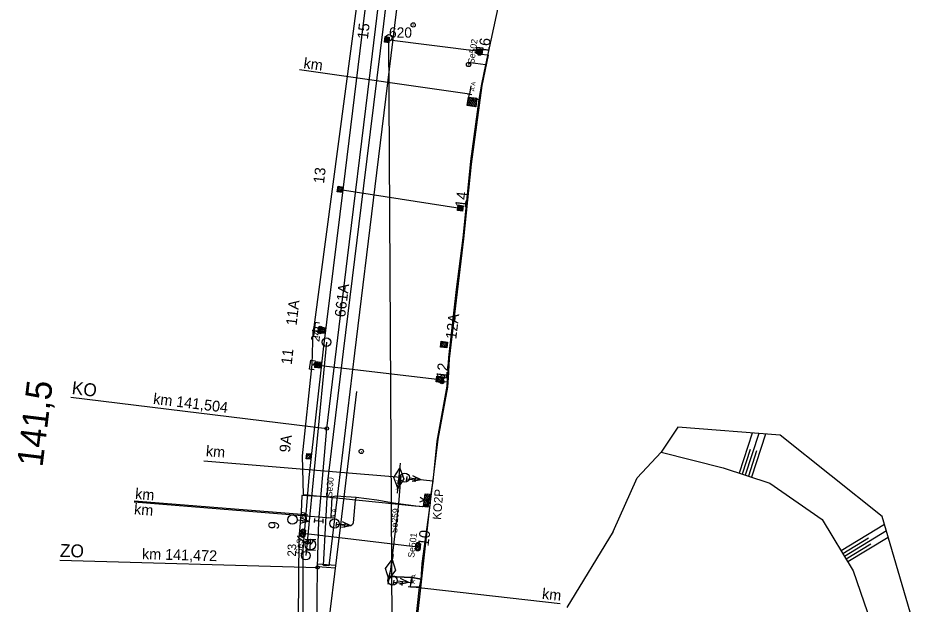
# Model space of a CAD drawing. Extents: x -598638 to -597933, y -1164002 to -1161904.
# Drawn here: x -598562.8 to -598354.3, y -1163078.8 to -1162942.3 of the extents above; entities that cross this region are included whole.
import ezdxf

# ---------------------------------------------------------------- set-up
doc = ezdxf.new("R2010")
doc.units = 0
for name, color, linetype in [('Vrstva 1', 7, 'Continuous'), ('Vrstva 11', 7, 'Continuous'), ('Vrstva 12', 7, 'Continuous'), ('Vrstva 17', 7, 'Continuous'), ('Vrstva 25', 7, 'Continuous'), ('Vrstva 26', 7, 'Continuous'), ('Vrstva 28', 7, 'Continuous'), ('Vrstva 3', 7, 'Continuous'), ('Vrstva 31', 7, 'Continuous'), ('Vrstva 35', 7, 'Continuous'), ('Vrstva 4', 7, 'Continuous'), ('Vrstva 43', 7, 'Continuous'), ('Vrstva 44', 7, 'Continuous'), ('Vrstva 48', 7, 'Continuous'), ('Vrstva 49', 7, 'Continuous'), ('Vrstva 51', 7, 'Continuous'), ('Vrstva 6', 7, 'Continuous'), ('Vrstva 63', 7, 'Continuous'), ('Vrstva 7', 7, 'Continuous')]:
    doc.layers.add(name, color=color, linetype=linetype)

msp = doc.modelspace()

# ---------------------------------------------------------------- linework, layer by layer
at = {"layer": 'Vrstva 1'}
for p, q in [((-598550.48, -1163030.61), (-598490.92, -1163037.88)), ((-598553.06, -1163068.55), (-598493.08, -1163070.23))]:
    msp.add_line(p, q, dxfattribs=at)
for points in [[(-598490.92, -1163037.88), (-598486.08, -1162998.23), (-598481.36, -1162959.57), (-598476.09, -1162916.14)], [(-598491.49, -1163091.37), (-598487.69, -1163060.3), (-598483.91, -1163029.31)], [(-598493.08, -1163070.23), (-598492.78, -1163059.37), (-598490.92, -1163037.88)], [(-598493.3, -1163091.17), (-598493.08, -1163070.23)]]:
    msp.add_lwpolyline(points, dxfattribs=at)
for centre in [(-598490.92, -1163037.88), (-598493.08, -1163070.23)]:
    msp.add_circle(centre, 0.4, dxfattribs=at)
at = {"layer": 'Vrstva 11'}
for p, q in [((-598476.84, -1162947.85), (-598477.38, -1162947.12)), ((-598476.53, -1162947.64), (-598477.08, -1162946.89)), ((-598476.95, -1162947.37), (-598455.4, -1162950.04)), ((-598455.51, -1162950.53), (-598455.9, -1162950)), ((-598454.98, -1162950.61), (-598455.82, -1162949.48)), ((-598454.9, -1162950.09), (-598455.3, -1162949.55)), ((-598487.95, -1162982.73), (-598488.34, -1162982.2)), ((-598487.42, -1162982.81), (-598488.26, -1162981.68)), ((-598487.84, -1162982.24), (-598459.89, -1162986.59)), ((-598487.34, -1162982.29), (-598487.74, -1162981.75)), ((-598460, -1162987.08), (-598460.39, -1162986.55)), ((-598459.47, -1162987.16), (-598460.31, -1162986.03)), ((-598459.39, -1162986.64), (-598459.79, -1162986.1)), ((-598492.14, -1163015.48), (-598492.55, -1163014.97)), ((-598491.61, -1163015.54), (-598492.49, -1163014.44)), ((-598491.55, -1163015.02), (-598491.96, -1163014.5)), ((-598463.22, -1163018.89), (-598464.1, -1163017.79)), ((-598463.16, -1163018.37), (-598463.58, -1163017.85)), ((-598463.75, -1163018.83), (-598464.16, -1163018.31)), ((-598493.03, -1163023.61), (-598493.44, -1163023.09)), ((-598492.5, -1163023.67), (-598493.38, -1163022.57)), ((-598492.94, -1163023.12), (-598464.66, -1163026.47)), ((-598492.44, -1163023.15), (-598492.85, -1163022.63)), ((-598464.75, -1163026.96), (-598465.16, -1163026.45)), ((-598464.22, -1163027.02), (-598465.1, -1163025.92)), ((-598464.16, -1163026.5), (-598464.58, -1163025.98)), ((-598495.62, -1163044.57), (-598494.97, -1163043.93)), ((-598495.36, -1163044.84), (-598494.71, -1163044.19)), ((-598496.3, -1163062.24), (-598496.85, -1163061.54)), ((-598495.99, -1163062.03), (-598496.58, -1163061.29)), ((-598496.41, -1163063.24), (-598496.97, -1163062.54)), ((-598496.1, -1163063.02), (-598496.69, -1163062.28)), ((-598496.46, -1163062.25), (-598469.73, -1163065.4)), ((-598469.68, -1163066.39), (-598470.24, -1163065.69)), ((-598469.57, -1163065.39), (-598470.12, -1163064.69)), ((-598469.37, -1163066.17), (-598469.96, -1163065.43)), ((-598469.26, -1163065.18), (-598469.85, -1163064.44))]:
    msp.add_line(p, q, dxfattribs=at)
for points in [[(-598455.97, -1162950.46), (-598455.82, -1162949.47), (-598454.83, -1162949.62), (-598454.98, -1162950.61)], [(-598488.41, -1162982.66), (-598488.26, -1162981.67), (-598487.27, -1162981.82), (-598487.42, -1162982.81)], [(-598460.46, -1162987.01), (-598460.31, -1162986.02), (-598459.32, -1162986.17), (-598459.47, -1162987.16)], [(-598492.6, -1163015.43), (-598492.49, -1163014.44), (-598491.5, -1163014.55), (-598491.61, -1163015.54)], [(-598464.21, -1163018.78), (-598464.1, -1163017.79), (-598463.11, -1163017.9), (-598463.22, -1163018.89)], [(-598493.49, -1163023.56), (-598493.38, -1163022.57), (-598492.39, -1163022.68), (-598492.5, -1163023.67)], [(-598465.21, -1163026.91), (-598465.1, -1163025.92), (-598464.11, -1163026.03), (-598464.22, -1163027.02)]]:
    msp.add_lwpolyline(points, close=True, dxfattribs=at)
for points in [[(-598455.97, -1162950.46), (-598455.82, -1162949.47), (-598454.83, -1162949.62), (-598454.98, -1162950.61), (-598455.97, -1162950.46)], [(-598488.41, -1162982.66), (-598488.26, -1162981.67), (-598487.27, -1162981.82), (-598487.42, -1162982.81), (-598488.41, -1162982.66)], [(-598460.46, -1162987.01), (-598460.31, -1162986.02), (-598459.32, -1162986.17), (-598459.47, -1162987.16), (-598460.46, -1162987.01)], [(-598492.6, -1163015.43), (-598492.49, -1163014.44), (-598491.5, -1163014.55), (-598491.61, -1163015.54), (-598492.6, -1163015.43)], [(-598464.21, -1163018.78), (-598464.1, -1163017.79), (-598463.11, -1163017.9), (-598463.22, -1163018.89), (-598464.21, -1163018.78)], [(-598493.49, -1163023.56), (-598493.38, -1163022.57), (-598492.39, -1163022.68), (-598492.5, -1163023.67), (-598493.49, -1163023.56)], [(-598465.21, -1163026.91), (-598465.1, -1163025.92), (-598464.11, -1163026.03), (-598464.22, -1163027.02), (-598465.21, -1163026.91)]]:
    msp.add_lwpolyline(points, dxfattribs=at)
for centre in [(-598476.95, -1162947.37), (-598495.16, -1163044.39), (-598496.4, -1163061.75), (-598496.4, -1163061.75), (-598496.52, -1163062.75), (-598496.52, -1163062.75), (-598469.79, -1163065.9), (-598469.79, -1163065.9), (-598469.67, -1163064.9), (-598469.67, -1163064.9)]:
    msp.add_circle(centre, 0.5, dxfattribs=at)
at = {"layer": 'Vrstva 12'}
for p, q in [((-598477.51, -1162947.97), (-598477.35, -1162946.67)), ((-598477.35, -1162946.67), (-598476.39, -1162946.76)), ((-598476.39, -1162946.76), (-598476.52, -1162948.08)), ((-598476.52, -1162948.08), (-598477.51, -1162947.97)), ((-598456.17, -1162950.62), (-598456.02, -1162949.1)), ((-598456.02, -1162949.1), (-598454.66, -1162949.26)), ((-598454.66, -1162949.26), (-598454.85, -1162950.8)), ((-598454.85, -1162950.8), (-598456.17, -1162950.62)), ((-598488.48, -1162982.79), (-598488.29, -1162981.48)), ((-598488.29, -1162981.48), (-598487.15, -1162981.68)), ((-598487.15, -1162981.68), (-598487.34, -1162982.95)), ((-598487.34, -1162982.95), (-598488.48, -1162982.79)), ((-598460.52, -1162987.15), (-598460.35, -1162985.85)), ((-598460.35, -1162985.85), (-598459.2, -1162986.04)), ((-598459.2, -1162986.04), (-598459.39, -1162987.33)), ((-598459.39, -1162987.33), (-598460.52, -1162987.15)), ((-598492.91, -1163015.59), (-598492.7, -1163014.12)), ((-598491.35, -1163015.78), (-598492.91, -1163015.59)), ((-598492.7, -1163014.12), (-598491.2, -1163014.43)), ((-598491.2, -1163014.43), (-598491.35, -1163015.78)), ((-598464.5, -1163018.94), (-598464.33, -1163017.57)), ((-598464.33, -1163017.57), (-598462.81, -1163017.78)), ((-598462.81, -1163017.78), (-598462.99, -1163019.11)), ((-598462.99, -1163019.11), (-598464.5, -1163018.94)), ((-598465.48, -1163027.04), (-598465.33, -1163025.71)), ((-598465.33, -1163025.71), (-598463.82, -1163025.86)), ((-598463.82, -1163025.86), (-598463.97, -1163027.25)), ((-598463.97, -1163027.25), (-598465.48, -1163027.04)), ((-598495.75, -1163044.99), (-598495.6, -1163043.69)), ((-598494.8, -1163045.06), (-598495.75, -1163044.99)), ((-598495.6, -1163043.69), (-598494.66, -1163043.77)), ((-598494.66, -1163043.77), (-598494.8, -1163045.06)), ((-598497.02, -1163062.94), (-598496.83, -1163061.46)), ((-598496.83, -1163061.46), (-598495.9, -1163061.57)), ((-598495.9, -1163061.57), (-598496.07, -1163063.05)), ((-598496.07, -1163063.05), (-598497.02, -1163062.94)), ((-598470.26, -1163066.05), (-598470.09, -1163064.6)), ((-598469.31, -1163066.19), (-598470.26, -1163066.05)), ((-598470.09, -1163064.6), (-598469.15, -1163064.72)), ((-598469.15, -1163064.72), (-598469.31, -1163066.19))]:
    msp.add_line(p, q, dxfattribs=at)
for points in [[(-598492.13, -1163022.54), (-598493.64, -1163022.36), (-598493.8, -1163023.69)], [(-598492.13, -1163022.54), (-598492.27, -1163023.87), (-598493.8, -1163023.69)]]:
    msp.add_lwpolyline(points, dxfattribs=at)
at = {"layer": 'Vrstva 17'}
for points in [[(-598492.59, -1163013.4), (-598493.67, -1163013.23), (-598494.03, -1163016.38), (-598492.93, -1163016.54)], [(-598493.88, -1163024.25), (-598494.98, -1163024.09), (-598494.68, -1163021.97), (-598493.58, -1163022.11)]]:
    msp.add_lwpolyline(points, dxfattribs=at)
at = {"layer": 'Vrstva 25'}
for p, q in [((-598455.45, -1162950.49), (-598455.35, -1162950.49)), ((-598492.59, -1163015.35), (-598492.49, -1163015.35)), ((-598492.49, -1163014.57), (-598492.39, -1163014.57)), ((-598493.46, -1163022.96), (-598493.36, -1163022.96)), ((-598464.02, -1163025.91), (-598463.92, -1163025.91)), ((-598464.18, -1163026.99), (-598464.08, -1163026.99)), ((-598494.75, -1163064.18), (-598494.65, -1163064.18))]:
    msp.add_line(p, q, dxfattribs=at)
for centre in [(-598455.4, -1162950.49), (-598492.54, -1163015.35), (-598492.44, -1163014.57), (-598493.41, -1163022.96), (-598463.97, -1163025.91), (-598464.13, -1163026.99), (-598494.7, -1163064.18)]:
    msp.add_circle(centre, 0.5, dxfattribs=at)
at = {"layer": 'Vrstva 26'}
for points in [[(-598493.83, -1163014.28), (-598480.89, -1162916.65), (-598479.84, -1162916.78), (-598473.65, -1162917.37), (-598473.49, -1162916.5)], [(-598471.78, -1163099.25), (-598466.96, -1163056.18), (-598464.99, -1163040.38), (-598462.78, -1163028.25), (-598462.7, -1163027.13), (-598462.63, -1163026.14), (-598462.35, -1163021.64), (-598459.07, -1162993.7), (-598457.28, -1162976.39), (-598454.77, -1162958.06), (-598453.28, -1162951.01)], [(-598453.28, -1162951.01), (-598455.22, -1162950.8), (-598455.4, -1162950.49)], [(-598466.96, -1163056.18), (-598470.44, -1163055.98), (-598496.35, -1163053.31), (-598496.61, -1163044.28), (-598494.3, -1163022.98), (-598494.1, -1163015.05), (-598493.83, -1163014.28), (-598492.66, -1163014.45), (-598492.44, -1163014.57)], [(-598494.1, -1163015.05), (-598492.8, -1163015.42), (-598492.54, -1163015.35)], [(-598494.3, -1163022.98), (-598493.6, -1163023.06), (-598493.41, -1163022.96)], [(-598462.63, -1163026.14), (-598463.61, -1163026.1), (-598463.97, -1163025.91)], [(-598462.7, -1163027.13), (-598463.79, -1163027.05), (-598464.13, -1163026.99)]]:
    msp.add_lwpolyline(points, dxfattribs=at)
at = {"layer": 'Vrstva 28'}
for p, q in [((-598457.98, -1162953.15), (-598457.88, -1162953.15)), ((-598475.35, -1163049.33), (-598473.95, -1163047.14)), ((-598473.82, -1163045.98), (-598474.56, -1163052.92)), ((-598473.95, -1163047.14), (-598473.03, -1163049.57)), ((-598474.43, -1163051.76), (-598475.35, -1163049.33)), ((-598473.03, -1163049.57), (-598474.43, -1163051.76)), ((-598467.2, -1163054.32), (-598468.07, -1163053.21)), ((-598467.14, -1163053.8), (-598467.66, -1163053.13)), ((-598467.07, -1163053.27), (-598467.13, -1163053.19)), ((-598467.68, -1163056.15), (-598468.33, -1163055.32)), ((-598467.39, -1163055.9), (-598468.26, -1163054.79)), ((-598467.33, -1163055.38), (-598468.2, -1163054.26)), ((-598467.26, -1163054.85), (-598468.14, -1163053.74)), ((-598468.2, -1163056.08), (-598468.39, -1163055.84)), ((-598475.49, -1163067.26), (-598476.69, -1163074.14)), ((-598477.24, -1163070.5), (-598475.69, -1163068.41)), ((-598475.69, -1163068.41), (-598474.94, -1163070.9)), ((-598476.49, -1163072.99), (-598477.24, -1163070.5)), ((-598474.94, -1163070.9), (-598476.49, -1163072.99))]:
    msp.add_line(p, q, dxfattribs=at)
for points in [[(-598450.89, -1162938.91), (-598454, -1162953.23), (-598454.97, -1162957.71), (-598455.57, -1162961.32), (-598457.46, -1162975.68), (-598459.28, -1162993.47), (-598460.85, -1163005.54), (-598462.59, -1163021.38), (-598462.99, -1163028.07), (-598465.31, -1163040.8), (-598466.26, -1163050.14), (-598466.84, -1163054.06), (-598466.91, -1163055.17), (-598468.81, -1163069.3), (-598469.03, -1163073.07), (-598469.42, -1163074.81)], [(-598454, -1162953.23), (-598457.49, -1162952.76), (-598457.93, -1162953.15)], [(-598455.57, -1162961.32), (-598456.78, -1162961.49), (-598458.1, -1162961.73), (-598457.7, -1162960.06)], [(-598473.68, -1163049.21), (-598473.95, -1163048.74), (-598474.19, -1163049.45), (-598473.95, -1163051.51), (-598474.23, -1163055.44), (-598476.09, -1163070.7), (-598476.46, -1163072.34), (-598471.11, -1163072.59), (-598469.38, -1163072.88), (-598469.03, -1163073.07)], [(-598466.26, -1163050.14), (-598468.45, -1163049.94), (-598468.96, -1163049.82)], [(-598466.91, -1163055.17), (-598468.72, -1163056.12), (-598470.23, -1163055.94), (-598474.23, -1163055.44), (-598475.44, -1163055.28), (-598479.31, -1163054.6), (-598484.13, -1163053.97), (-598488.8, -1163053.64), (-598489.73, -1163053.89), (-598496.7, -1163053.51), (-598496.9, -1163057.39), (-598497.4, -1163063.32), (-598497.67, -1163091.49), (-598498.51, -1163106.98), (-598497.94, -1163116.3), (-598497.72, -1163118), (-598498.27, -1163121.17), (-598498.4, -1163124.98), (-598499.21, -1163133.4), (-598493.91, -1163133.54), (-598493.16, -1163125.93), (-598493.11, -1163125.49)], [(-598468.42, -1163056.06), (-598468.06, -1163053.08), (-598467.06, -1163053.2), (-598467.43, -1163056.18), (-598468.42, -1163056.06)], [(-598489.73, -1163053.89), (-598490.02, -1163058.34), (-598489.96, -1163058.72)], [(-598484.13, -1163053.97), (-598484.31, -1163054.51), (-598484.83, -1163059.83), (-598484.92, -1163060.26), (-598485.32, -1163060.55)], [(-598469.29, -1163054.95), (-598468.24, -1163054.57), (-598469.17, -1163053.95)], [(-598466.84, -1163054.06), (-598467.74, -1163054.63), (-598466.91, -1163055.17)], [(-598496.9, -1163057.39), (-598496.16, -1163057.53), (-598495.84, -1163057.94), (-598495.75, -1163059.26), (-598495.11, -1163059.51)], [(-598497.4, -1163063.32), (-598495.35, -1163064.79), (-598494.7, -1163064.18), (-598494.75, -1163064.94)], [(-598471.11, -1163072.59), (-598471.14, -1163073.86), (-598471.81, -1163073.74)], [(-598469.42, -1163074.81), (-598471.51, -1163074.74)], [(-598469.42, -1163074.81), (-598471.25, -1163091.17)]]:
    msp.add_lwpolyline(points, dxfattribs=at)
msp.add_lwpolyline([(-598468.42, -1163056.06), (-598468.06, -1163053.08), (-598467.06, -1163053.2), (-598467.43, -1163056.18)], close=True, dxfattribs=at)
msp.add_circle((-598457.93, -1162953.15), 0.5, dxfattribs=at)
at = {"layer": 'Vrstva 3'}
for p, q in [((-598457.31, -1162962.85), (-598458.11, -1162961.79)), ((-598456.78, -1162962.92), (-598458.04, -1162961.27)), ((-598456.25, -1162962.99), (-598457.97, -1162960.74)), ((-598456.18, -1162962.46), (-598457.45, -1162960.81)), ((-598456.11, -1162961.94), (-598456.92, -1162960.88)), ((-598456.04, -1162961.41), (-598456.4, -1162960.95)), ((-598457.83, -1162962.78), (-598458.18, -1162962.32)), ((-598472.37, -1163050.09), (-598472.25, -1163049.1)), ((-598468.96, -1163049.82), (-598470.93, -1163048.88)), ((-598470.39, -1163050.34), (-598470.27, -1163049.34)), ((-598472.31, -1163049.6), (-598470.33, -1163049.84)), ((-598468.96, -1163049.82), (-598471.7, -1163049.49)), ((-598468.96, -1163049.82), (-598471.1, -1163050.25)), ((-598495.11, -1163059.51), (-598497.85, -1163059.21)), ((-598495.11, -1163059.51), (-598497.24, -1163059.97)), ((-598495.11, -1163059.51), (-598497.09, -1163058.6)), ((-598493.81, -1163059.81), (-598493.75, -1163058.81)), ((-598493.78, -1163059.31), (-598491.78, -1163059.43)), ((-598491.81, -1163059.93), (-598491.75, -1163058.93)), ((-598488.75, -1163060.68), (-598488.63, -1163059.68)), ((-598485.32, -1163060.55), (-598487.28, -1163059.58)), ((-598488.69, -1163060.18), (-598486.7, -1163060.42)), ((-598485.32, -1163060.55), (-598488.05, -1163060.17)), ((-598485.32, -1163060.55), (-598487.47, -1163060.95)), ((-598486.76, -1163060.92), (-598486.64, -1163059.93)), ((-598495.96, -1163063.69), (-598493.5, -1163063.73)), ((-598494.77, -1163066.17), (-598494.73, -1163063.71)), ((-598496, -1163066.15), (-598493.54, -1163066.19)), ((-598475.39, -1163074.17), (-598475.27, -1163073.17)), ((-598475.33, -1163073.67), (-598473.35, -1163073.91)), ((-598471.81, -1163073.74), (-598474.55, -1163073.41)), ((-598471.81, -1163073.74), (-598473.95, -1163074.17)), ((-598471.81, -1163073.74), (-598473.78, -1163072.8)), ((-598473.41, -1163074.41), (-598473.29, -1163073.42))]:
    msp.add_line(p, q, dxfattribs=at)
msp.add_lwpolyline([(-598458.24, -1162962.73), (-598457.97, -1162960.74), (-598455.99, -1162961.01), (-598456.25, -1162962.99)], close=True, dxfattribs=at)
msp.add_lwpolyline([(-598458.24, -1162962.73), (-598457.97, -1162960.74), (-598455.99, -1162961.01), (-598456.25, -1162962.99)], close=True, dxfattribs=at)
msp.add_lwpolyline([(-598458.24, -1162962.73), (-598457.97, -1162960.74), (-598455.99, -1162961.01), (-598456.25, -1162962.99), (-598458.24, -1162962.73)], dxfattribs=at)
msp.add_lwpolyline([(-598458.24, -1162962.73), (-598457.97, -1162960.74), (-598455.99, -1162961.01), (-598456.25, -1162962.99), (-598458.24, -1162962.73)], dxfattribs=at)
for centre, radius in [((-598472.77, -1163049.33), 1.08), ((-598498.93, -1163059.09), 1.08), ((-598489.12, -1163060.01), 1.08), ((-598494.75, -1163064.94), 1.23), ((-598475.62, -1163073.27), 1.08)]:
    msp.add_circle(centre, radius, dxfattribs=at)
at = {"layer": 'Vrstva 31'}
msp.add_lwpolyline([(-598450.89, -1162938.91), (-598454, -1162953.23), (-598454.97, -1162957.71), (-598455.57, -1162961.32), (-598457.46, -1162975.68), (-598459.28, -1162993.47), (-598460.85, -1163005.54), (-598462.59, -1163021.38), (-598462.99, -1163028.07), (-598465.31, -1163040.8), (-598466.26, -1163050.14), (-598466.84, -1163054.06), (-598466.91, -1163055.17), (-598468.81, -1163069.3), (-598469.03, -1163073.07), (-598469.42, -1163074.81), (-598471.25, -1163091.17)], dxfattribs=at)
at = {"layer": 'Vrstva 35'}
for points in [[(-598468.72, -1163056.12), (-598470.23, -1163055.94), (-598474.23, -1163055.44), (-598475.44, -1163055.28), (-598479.31, -1163054.6), (-598484.13, -1163053.97), (-598488.8, -1163053.64), (-598489.73, -1163053.89), (-598496.7, -1163053.51)], [(-598469.38, -1163072.88), (-598471.11, -1163072.59), (-598476.46, -1163072.34)]]:
    msp.add_lwpolyline(points, dxfattribs=at)
at = {"layer": 'Vrstva 4'}
msp.add_lwpolyline([(-598498.34, -1163129.68), (-598496.71, -1163105.39), (-598496.44, -1163083.97), (-598496.41, -1163066.1), (-598495.03, -1163049.33), (-598491.68, -1163019.45), (-598487.03, -1162981.73), (-598482.3, -1162943.02), (-598477.41, -1162904.76), (-598474.84, -1162891.5), (-598471.73, -1162876.6)], dxfattribs=at)
at = {"layer": 'Vrstva 43'}
for centre in [(-598490.97, -1163017.79), (-598495.81, -1163067.49)]:
    msp.add_circle(centre, 1, dxfattribs=at)
at = {"layer": 'Vrstva 44'}
msp.add_lwpolyline([(-598490.97, -1163017.79), (-598495.81, -1163067.49)], dxfattribs=at)
at = {"layer": 'Vrstva 48'}
for p, q in [((-598391.94, -1163038.95), (-598394.97, -1163048.27)), ((-598390.41, -1163039.07), (-598393.55, -1163048.73)), ((-598388.87, -1163039.19), (-598392.13, -1163049.19)), ((-598392.41, -1163042.81), (-598394.26, -1163048.5)), ((-598390.92, -1163043.06), (-598392.84, -1163048.96)), ((-598361.14, -1163060.26), (-598371.26, -1163066.39)), ((-598360.71, -1163061.75), (-598370.48, -1163067.68)), ((-598364.9, -1163063.42), (-598370.87, -1163067.04)), ((-598360.28, -1163063.24), (-598369.7, -1163068.96)), ((-598364.33, -1163064.82), (-598370.09, -1163068.32))]:
    msp.add_line(p, q, dxfattribs=at)
at = {"layer": 'Vrstva 49'}
msp.add_line((-598424.28, -1163061.86), (-598435.05, -1163079.55), dxfattribs=at)
for points in [[(-598385.15, -1163145.56), (-598373.83, -1163129.54), (-598369.51, -1163122.92), (-598366.65, -1163122.76), (-598356.04, -1163109.13), (-598357.76, -1163100.76), (-598354.29, -1163083.84), (-598361.7, -1163058.35), (-598385.44, -1163039.46), (-598409.22, -1163037.61), (-598413.1, -1163043.39)], [(-598424.28, -1163061.86), (-598418.7, -1163049.38), (-598413.1, -1163043.39), (-598398.68, -1163047.06), (-598387.83, -1163050.59), (-598375.69, -1163059.09), (-598368.44, -1163071.04), (-598363.48, -1163085.45), (-598363.57, -1163099.08), (-598365.65, -1163107.4), (-598374.33, -1163116.48), (-598382.2, -1163132.26), (-598385.15, -1163145.56)]]:
    msp.add_lwpolyline(points, dxfattribs=at)
at = {"layer": 'Vrstva 51'}
msp.add_lwpolyline([(-598491.72, -1163069.8), (-598490.59, -1163049.57), (-598487.01, -1163019.97), (-598482.28, -1162981.39), (-598477.64, -1162943.65), (-598473.3, -1162907.34), (-598468.37, -1162876.99), (-598466.96, -1162877.17), (-598470.72, -1162908.17), (-598475.15, -1162944.09), (-598479.77, -1162981.58), (-598484.51, -1163020.39), (-598490.47, -1163069.86), (-598491.72, -1163069.8)], dxfattribs=at)
at = {"layer": 'Vrstva 6'}
for p, q in [((-598457.7, -1162960.06), (-598497.3, -1162954.4)), ((-598457.42, -1162958.1), (-598457.7, -1162960.06)), ((-598458.2, -1162959.99), (-598457.21, -1162960.13)), ((-598519.51, -1163045.45), (-598473.68, -1163049.21)), ((-598473.18, -1163049.25), (-598474.18, -1163049.17)), ((-598473.84, -1163051.18), (-598473.68, -1163049.21)), ((-598535.77, -1163055), (-598489.96, -1163058.72)), ((-598535.71, -1163054.71), (-598495.84, -1163057.94)), ((-598496.34, -1163057.9), (-598495.34, -1163057.98)), ((-598489.46, -1163058.76), (-598490.46, -1163058.68)), ((-598471.29, -1163072.78), (-598471.51, -1163074.74)), ((-598472.01, -1163074.69), (-598471.01, -1163074.8)), ((-598436.62, -1163078.71), (-598471.51, -1163074.74))]:
    msp.add_line(p, q, dxfattribs=at)
at = {"layer": 'Vrstva 63'}
for p, q in [((-598476.51, -1162946.91), (-598476.41, -1162946.91)), ((-598475.57, -1163109.93), (-598476.46, -1162946.91))]:
    msp.add_line(p, q, dxfattribs=at)
msp.add_circle((-598476.46, -1162946.91), 0.756, dxfattribs=at)
at = {"layer": 'Vrstva 7'}
for p, q in [((-598470.88, -1162943.94), (-598470.78, -1162943.94)), ((-598482.97, -1163043.22), (-598482.87, -1163043.22)), ((-598488.93, -1163070.41), (-598493.08, -1163070.1)), ((-598488.86, -1163069.81), (-598493.06, -1163069.5))]:
    msp.add_line(p, q, dxfattribs=at)
for centre in [(-598470.83, -1162943.94), (-598482.92, -1163043.22)]:
    msp.add_circle(centre, 0.5, dxfattribs=at)

# ---------------------------------------------------------------- texts
at = {"layer": 'Vrstva 1'}
for s, height, rotation, p in [('661A', 2.5, 83.0372, (-598486.66, -1163012.08)), ('KO', 3, 353.0372, (-598550.38, -1163029.84)), ('km 141,504', 2.5, 353.0619, (-598531.42, -1163032.15)), ('ZO', 3, 358.3961, (-598553.04, -1163067.77)), ('km 141,472', 2.5, 358.4208, (-598533.95, -1163068.3))]:
    msp.add_text(s, height=height, rotation=rotation, dxfattribs=at).set_placement(p)
at = {"layer": 'Vrstva 11'}
for s, p in [('15', (-598481.38, -1162947.37)), ('16', (-598453.23, -1162950.8)), ('13', (-598491.59, -1162980.96)), ('14', (-598458.62, -1162986.59)), ('11A', (-598497.97, -1163014.02)), ('12A', (-598460.81, -1163017.21)), ('11', (-598499.1, -1163023.12)), ('12', (-598463.01, -1163026.47)), ('9A', (-598499.52, -1163043.57)), ('9', (-598502.14, -1163061.49)), ('10', (-598467.27, -1163065.4))]:
    msp.add_text(s, height=2.5, rotation=83.2508, dxfattribs=at).set_placement(p)
at = {"layer": 'Vrstva 28'}
msp.add_text('KO2P', height=2, rotation=85.6077, dxfattribs=at).set_placement((-598464.35, -1163059.19))
at = {"layer": 'Vrstva 43'}
for s, rotation, p in [('24', 83.0372, (-598492.67, -1163017.79)), ('23', 88.3961, (-598498.11, -1163067.74))]:
    msp.add_text(s, height=2, rotation=rotation, dxfattribs=at).set_placement(p)
at = {"layer": 'Vrstva 6'}
for s, height, rotation, p in [('Se502', 1.5, 81.8636, (-598456.65, -1162953.09)), ('km ', 2.5, 351.8636, (-598496.46, -1162953.99)), ('  A A', 1, 81.8636, (-598456.71, -1162960.2)), ('km ', 2.5, 355.3086, (-598519.13, -1163044.31)), ('Se30', 1.5, 85.3624, (-598489.68, -1163053.95)), ('  A A', 1, 265.3086, (-598474.68, -1163049.13)), ('km ', 2.5, 355.3624, (-598535.59, -1163054.28)), ('km ', 2.5, 355.3624, (-598535.84, -1163057.85)), ('A A', 1, 85.3624, (-598488.96, -1163058.8)), ('Se259', 1.5, 85.3086, (-598474.59, -1163062.32)), ('A A', 1, 265.3624, (-598496.84, -1163057.86)), ('Se31', 1.5, 85.3624, (-598496.69, -1163067.2)), ('Se501', 1.5, 83.519, (-598470.59, -1163068.02)), ('  A A', 1, 83.519, (-598470.51, -1163074.86)), ('km ', 2.5, 353.519, (-598440.94, -1163077.53))]:
    msp.add_text(s, height=height, rotation=rotation, dxfattribs=at).set_placement(p)
at = {"layer": 'Vrstva 63'}
msp.add_text('620', height=2.4, dxfattribs=at).set_placement((-598476.46, -1162946.91))
at = {"layer": 'Vrstva 7'}
msp.add_text('141,5', height=6, rotation=83.0393, dxfattribs=at).set_placement((-598557.09, -1163047.01))

doc.saveas('drawing.dxf')
